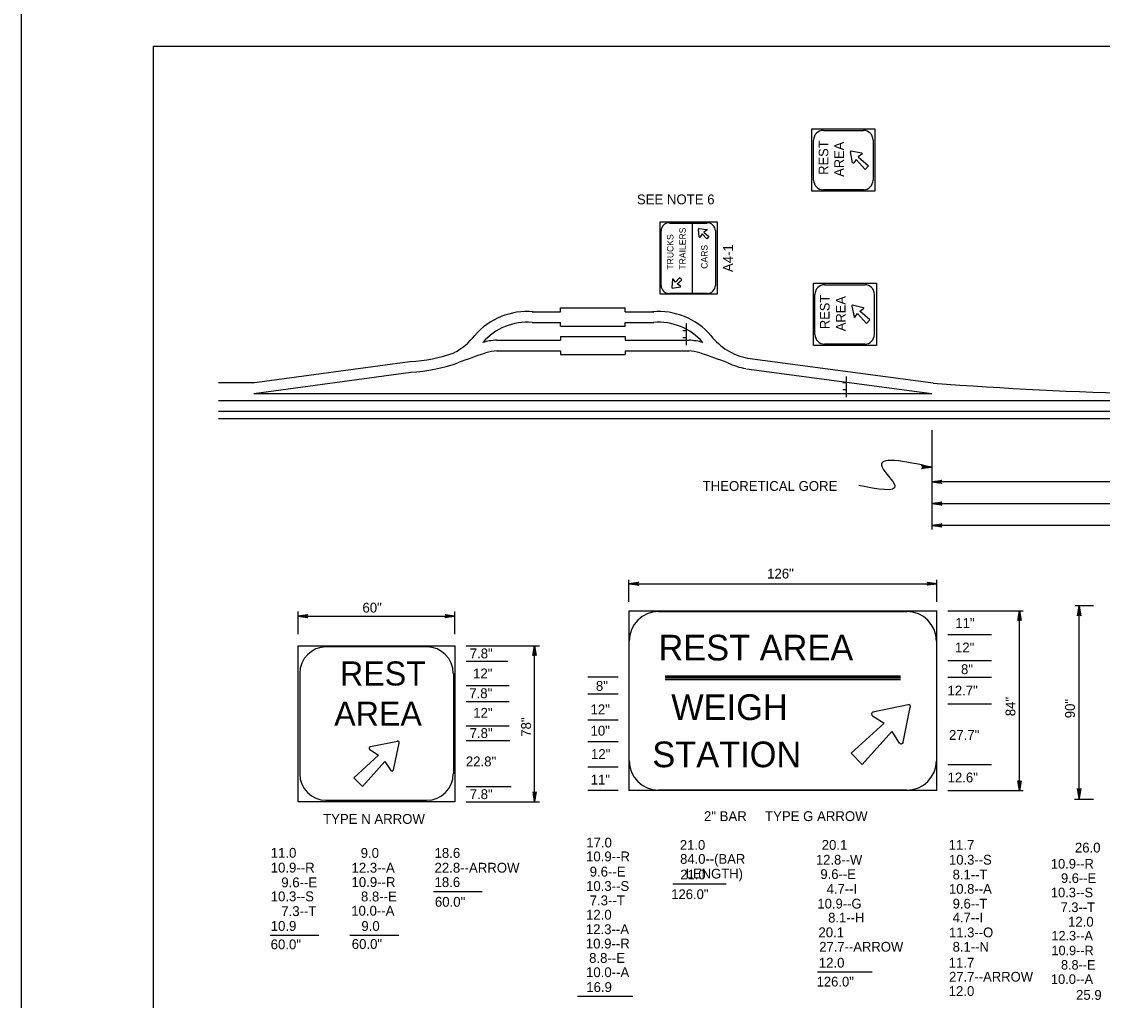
# Model space of a CAD drawing. Extents: x 649604 to 650509, y 298458 to 299646.
# Drawn here: x 649604.3 to 649933.2, y 298746.1 to 299044.1 of the extents above; entities that cross this region are included whole.
import ezdxf

# ---------------------------------------------------------------- set-up
doc = ezdxf.new("R2010")
doc.units = 0
for name, color, linetype in [('1', 7, 'Continuous'), ('2', 7, 'Continuous'), ('3', 7, 'Continuous'), ('PLT-BNDY', 7, 'Continuous')]:
    doc.layers.add(name, color=color, linetype=linetype)

# ---------------------------------------------------------------- blocks, each defined once
blk = doc.blocks.new('RARROW')
at = {"layer": '3'}
blk.add_lwpolyline([(-2.2695, 0.285), (-2.184875, 0.12075), (0, 0), (-2.2695, 0.285), (-2.38575, 0.384625), (0, 0), (-2.183125, -0.108), (-2.262875, -0.2705), (0, 0), (-2.38575, -0.379125), (-2.262875, -0.2705)], dxfattribs=at)

msp = doc.modelspace()

# ---------------------------------------------------------------- linework, layer by layer
at = {"layer": '1'}
for q in [(650430.31, 299036.63), (649644.31, 298472.63)]:
    msp.add_line((649644.31, 299036.63), q, dxfattribs=at)
at = {"layer": '2'}
for p, q in [((649848.31, 299011), (649860.56, 299011)), ((649856.56, 299004.75), (649856.56, 299004.75)), ((649857.19, 299001.13), (649856.56, 299004.5)), ((649856.69, 299004.75), (649860.06, 299004.13)), ((649860.06, 299003.75), (649858.94, 299003)), ((649858.31, 299002.13), (649857.56, 299001.13)), ((649861.06, 298999.13), (649858.31, 299002.13)), ((649858.31, 299002.13), (649858.31, 299002.13)), ((649858.94, 299003), (649858.94, 299003)), ((649858.94, 299003), (649862.06, 299000.25)), ((649862.06, 299000.25), (649861.06, 298999.13)), ((649863.94, 298992.5), (649844.81, 298992.5)), ((649860.56, 298992.88), (649848.31, 298992.88)), ((649801.44, 298982.75), (649812.94, 298982.75)), ((649808.44, 298961.5), (649808.44, 298982.75)), ((649810.56, 298978.63), (649810.31, 298980.88)), ((649810.56, 298981.13), (649812.81, 298980.88)), ((649810.56, 298981), (649810.56, 298981)), ((649812.81, 298980.63), (649811.94, 298980)), ((649812.81, 298980.63), (649812.81, 298980.63)), ((649812.94, 298980.63), (649812.94, 298980.63)), ((649812.94, 298980.63), (649812.94, 298980.63)), ((649810.69, 298978.63), (649810.69, 298978.63)), ((649810.69, 298978.38), (649810.69, 298978.38)), ((649810.69, 298978.38), (649810.69, 298978.38)), ((649811.44, 298979.5), (649810.81, 298978.5)), ((649812.81, 298978), (649811.44, 298979.5)), ((649811.44, 298979.5), (649811.44, 298979.5)), ((649811.69, 298979.75), (649811.69, 298979.75)), ((649811.94, 298980), (649811.94, 298980)), ((649811.94, 298980), (649813.44, 298978.75)), ((649813.44, 298978.75), (649812.81, 298978)), ((649812.81, 298978), (649812.81, 298978)), ((649813.44, 298978.75), (649813.44, 298978.75)), ((649802.44, 298965.63), (649802.19, 298963.25)), ((649802.56, 298965.88), (649802.56, 298965.88)), ((649803.31, 298964.75), (649802.69, 298965.63)), ((649804.56, 298966.13), (649803.31, 298964.75)), ((649803.81, 298964.25), (649805.19, 298965.5)), ((649803.81, 298964.25), (649803.81, 298964.25)), ((649804.81, 298963.63), (649803.81, 298964.25)), ((649805.19, 298965.5), (649804.56, 298966.13)), ((649800.94, 298961.13), (649799.31, 298961.13)), ((649801.44, 298961.5), (649812.94, 298961.5)), ((649802.19, 298963.13), (649802.19, 298963.13)), ((649802.31, 298963), (649804.81, 298963.38)), ((649804.81, 298963.5), (649804.81, 298963.5)), ((649804.81, 298963.5), (649804.81, 298963.5)), ((649808.81, 298961.13), (649807.81, 298961.13)), ((649848.69, 298964), (649860.94, 298964)), ((649856.81, 298957.75), (649856.81, 298957.75)), ((649860.44, 298957), (649857.19, 298957.75)), ((649759.69, 298955.75), (649768.31, 298955.75)), ((649768.31, 298957), (649787.94, 298957)), ((649768.31, 298955.75), (649768.31, 298957)), ((649787.94, 298955.75), (649787.94, 298957)), ((649787.94, 298955.75), (649796.69, 298955.75)), ((649856.94, 298957.5), (649857.69, 298954.25)), ((649857.94, 298954.25), (649858.69, 298955.25)), ((649858.69, 298955.25), (649858.69, 298955.25)), ((649858.69, 298955.25), (649861.44, 298952.25)), ((649859.44, 298956), (649860.56, 298956.75)), ((649862.44, 298953.38), (649859.44, 298956)), ((649859.44, 298956), (649859.44, 298956)), ((649860.94, 298957), (649860.94, 298957)), ((649759.69, 298952.5), (649768.31, 298952.5)), ((649768.31, 298951.38), (649768.31, 298952.5)), ((649768.31, 298951.38), (649787.94, 298951.38)), ((649787.94, 298951.38), (649787.94, 298952.5)), ((649787.94, 298952.5), (649796.69, 298952.5)), ((649806.69, 298945.63), (649806.69, 298952.25)), ((649857.81, 298953.75), (649857.81, 298953.75)), ((649861.44, 298952.25), (649862.44, 298953.38)), ((649768.31, 298948.25), (649787.94, 298948.25)), ((649768.31, 298948.25), (649768.31, 298947.13)), ((649787.94, 298948.25), (649787.94, 298947.13)), ((649806.69, 298950), (649805.56, 298950)), ((649806.69, 298947.88), (649805.56, 298947.88)), ((649748.81, 298947.13), (649768.31, 298947.13)), ((649787.94, 298947.13), (649807.44, 298947.13)), ((649864.44, 298945.5), (649845.31, 298945.5)), ((649860.94, 298945.88), (649848.69, 298945.88)), ((649748.81, 298943.88), (649768.31, 298943.88)), ((649768.31, 298943.88), (649768.31, 298942.75)), ((649768.31, 298942.75), (649787.94, 298942.75)), ((649787.94, 298943.88), (649787.94, 298942.75)), ((649787.94, 298943.88), (649807.44, 298943.88)), ((649825.19, 298941.63), (649881.69, 298934.13)), ((649674.44, 298934.13), (649722.44, 298940.63)), ((649824.94, 298938.38), (649824.94, 298938.38)), ((649824.94, 298938.38), (649881.31, 298930.88)), ((649674.94, 298930.88), (649722.81, 298937.38)), ((649722.81, 298937.38), (649722.81, 298937.38)), ((649722.81, 298937.38), (649722.81, 298937.38)), ((649855.31, 298929.75), (649855.31, 298936.13)), ((649674.94, 298934.13), (649664.19, 298934.13)), ((649855.31, 298934.13), (649854.19, 298934.13)), ((649855.31, 298932), (649854.19, 298932)), ((649664.19, 298928.75), (650390.69, 298928.75)), ((649674.94, 298930.88), (649881.31, 298930.88)), ((649674.94, 298930.88), (649674.94, 298930.88)), ((649674.94, 298930.88), (649674.94, 298930.88)), ((649664.19, 298925.5), (650390.69, 298925.5)), ((649664.19, 298923.25), (650390.69, 298923.25)), ((649881.31, 298919.75), (649881.31, 298889.5)), ((650085.69, 298904), (649881.31, 298904)), ((649881.31, 298897.38), (650176.94, 298897.38)), ((650311.69, 298890.75), (649881.31, 298890.75)), ((649789.13, 298867.47), (649789.13, 298874.13)), ((649789.13, 298873), (649882.88, 298873)), ((649882.88, 298867.47), (649882.88, 298874.13)), ((649930.47, 298866.25), (649924.9, 298866.25)), ((649926.15, 298807.63), (649926.15, 298866.25)), ((649688.44, 298857.65), (649688.44, 298864.5)), ((649688.44, 298863.13), (649736.19, 298863.13)), ((649736.19, 298857.65), (649736.19, 298864.5)), ((649789.13, 298864.75), (649882.88, 298864.75)), ((649789.13, 298864.75), (649789.13, 298810)), ((649798.15, 298864.49), (649873.75, 298864.49)), ((649882.88, 298810), (649882.88, 298864.75)), ((649886.17, 298864.75), (649909.12, 298864.75)), ((649908, 298810), (649908, 298864.75)), ((649886.17, 298857.5), (649899.45, 298857.5)), ((649688.44, 298806.63), (649688.44, 298854.13)), ((649739.56, 298854.13), (649761.94, 298854.13)), ((649760.44, 298806.63), (649760.44, 298854.13)), ((649789.21, 298819.06), (649789.21, 298855.55)), ((649882.7, 298855.55), (649882.7, 298819.06)), ((649739.56, 298849.38), (649752.33, 298849.38)), ((649886.17, 298849.63), (649899.45, 298849.63)), ((649688.94, 298845.63), (649688.94, 298815.13)), ((649735.81, 298815.13), (649735.81, 298845.63)), ((649785.9, 298844.5), (649776.63, 298844.5)), ((649800.13, 298845), (649871.76, 298845)), ((649800.13, 298844.88), (649871.76, 298844.88)), ((649800.13, 298844.5), (649871.76, 298844.5)), ((649800.13, 298844), (649871.76, 298844)), ((649800.13, 298843.88), (649871.76, 298843.88)), ((649886.17, 298844.5), (649899.45, 298844.5)), ((649739.56, 298842), (649752.68, 298842)), ((649785.9, 298839.38), (649776.63, 298839.38)), ((649739.56, 298837.13), (649752.68, 298837.13)), ((649874.13, 298836.13), (649863.38, 298833.88)), ((649874.13, 298836.13), (649863.38, 298833.88)), ((649875.01, 298836.38), (649875.01, 298836.38)), ((649886.17, 298836.38), (649899.45, 298836.38)), ((649862.01, 298833.63), (649862.01, 298833.63)), ((649863.26, 298832.75), (649866.76, 298830.5)), ((649863.26, 298832.75), (649866.76, 298830.5)), ((649872.63, 298824.75), (649874.76, 298835.38)), ((649872.63, 298824.75), (649874.76, 298835.38)), ((649739.56, 298829.75), (649752.68, 298829.75)), ((649785.9, 298831.5), (649776.63, 298831.5)), ((649866.76, 298830.5), (649856.76, 298821.38)), ((649866.76, 298830.5), (649856.76, 298821.38)), ((649866.76, 298830.5), (649866.76, 298830.5)), ((649867.88, 298829.25), (649867.88, 298829.25)), ((649860.13, 298818), (649869.13, 298828)), ((649860.13, 298818), (649869.13, 298828)), ((649869.13, 298828), (649871.38, 298824.5)), ((649869.13, 298828), (649869.13, 298828)), ((649869.13, 298828), (649871.38, 298824.5)), ((649709.31, 298823.13), (649709.31, 298823.13)), ((649718.69, 298825), (649710.44, 298823.38)), ((649717.44, 298816.38), (649719.19, 298824.5)), ((649719.31, 298825.25), (649719.31, 298825.25)), ((649739.56, 298825.25), (649752.91, 298825.25)), ((649785.9, 298824.88), (649776.63, 298824.88)), ((649872.38, 298823.25), (649872.38, 298823.25)), ((649712.94, 298820.75), (649705.44, 298813.88)), ((649710.31, 298822.5), (649712.94, 298820.75)), ((649712.94, 298820.75), (649712.94, 298820.75)), ((649856.76, 298821.38), (649860.13, 298818)), ((649856.76, 298821.38), (649856.76, 298821.38)), ((649856.76, 298821.38), (649860.13, 298818)), ((649708.06, 298811.25), (649714.81, 298818.88)), ((649714.81, 298818.88), (649714.81, 298818.88)), ((649714.81, 298818.88), (649716.69, 298816.13)), ((649785.9, 298817.13), (649776.63, 298817.13)), ((649860.13, 298818), (649860.13, 298818)), ((649886.17, 298818), (649899.45, 298818)), ((649705.44, 298813.88), (649708.06, 298811.25)), ((649717.19, 298815.25), (649717.19, 298815.25)), ((649739.56, 298811.25), (649753.26, 298811.25)), ((649785.9, 298810), (649776.63, 298810)), ((649882.88, 298810), (649789.13, 298810)), ((649873.75, 298810.12), (649798.15, 298810.12)), ((649886.17, 298810), (649909.12, 298810)), ((649739.56, 298806.63), (649761.94, 298806.63)), ((649930.47, 298807.27), (649924.77, 298807.27)), ((649802.47, 298781.61), (649818.72, 298781.61)), ((649729.65, 298779.34), (649744.51, 298779.34)), ((649679.92, 298765.97), (649694.77, 298765.97)), ((649704.19, 298765.97), (649719.1, 298765.97)), ((649846.53, 298754.86), (649863.15, 298754.86)), ((649773.49, 298747.38), (649790.28, 298747.38))]:
    msp.add_line(p, q, dxfattribs=at)
for points in [[(649844.81, 298992.5), (649844.81, 299011.5), (649846.81, 299011.5), (649849.81, 299011.5), (649851.69, 299011.5), (649854.56, 299011.5), (649856.56, 299011.5), (649862.19, 299011.5), (649863.94, 299011.5), (649863.94, 299011.5), (649863.94, 298992.5), (649863.94, 298992.5)], [(649845.31, 298995.88), (649845.31, 299008.13)], [(649863.44, 299008.13), (649863.44, 298995.88)], [(649798.69, 298961.13), (649798.69, 298983.13), (649800.31, 298983.13), (649802.19, 298983.13), (649803.69, 298983.13), (649805.69, 298983.13), (649807.06, 298983.13), (649808.56, 298983.13), (649811.81, 298983.13), (649815.94, 298983.13), (649815.94, 298961.13), (649811.19, 298961.13), (649809.31, 298961.13), (649807.06, 298961.13), (649804.69, 298961.13), (649801.44, 298961.13), (649798.69, 298961.13)], [(649798.94, 298963.75), (649798.94, 298980.5)], [(649815.44, 298980.5), (649815.44, 298963.75)], [(649845.31, 298945.5), (649845.31, 298964.5), (649847.31, 298964.5), (649850.19, 298964.5), (649852.06, 298964.5), (649855.06, 298964.5), (649856.81, 298964.5), (649862.56, 298964.5), (649864.44, 298964.5), (649864.44, 298964.5), (649864.44, 298945.5), (649864.44, 298945.5)], [(649845.69, 298948.88), (649845.69, 298961.13)], [(649863.81, 298961.13), (649863.81, 298948.88)], [(649688.44, 298854.13), (649736.19, 298854.13), (649736.19, 298849.38), (649736.19, 298842), (649736.19, 298837.13), (649736.19, 298829.75), (649736.19, 298825.25), (649736.19, 298811.25), (649736.19, 298806.63), (649736.19, 298806.63), (649688.44, 298806.63), (649688.44, 298806.63)], [(649727.56, 298853.75), (649696.94, 298853.75)], [(649696.94, 298807.13), (649727.56, 298807.13)]]:
    msp.add_lwpolyline(points, dxfattribs=at)
for centre, radius, start, end in [((649848.27, 299008.08), 2.93, 90, 180), ((649860.49, 299008.08), 2.93, 0, 90), ((649856.7, 299004.54), 0.183, 78.0958, 191.9043), ((649856.7, 299004.54), 0.183, 78.0958, 191.9043), ((649859.98, 299003.85), 0.183, 302.692, 78.0958), ((649859.98, 299003.85), 0.183, 302.692, 78.0958), ((649857.39, 299001.26), 0.183, 191.9043, 327.308), ((649857.39, 299001.26), 0.183, 191.9042, 327.308), ((649848.27, 298995.86), 2.93, 180, 270), ((649860.49, 298995.86), 2.93, 270, 0), ((649801.36, 298980.44), 2.44, 90, 180), ((649810.44, 298981), 0.153, 84.0498, 185.9502), ((649812.84, 298980.75), 0.153, 301.5539, 84.0498), ((649812.99, 298980.44), 2.44, 0, 90), ((649810.69, 298978.6), 0.153, 185.9502, 328.4461), ((649802.55, 298965.61), 0.153, 31.5539, 174.0498), ((649801.36, 298963.82), 2.44, 180, 270), ((649802.3, 298963.22), 0.153, 174.0498, 275.9502), ((649804.69, 298963.47), 0.153, 275.9502, 58.4461), ((649812.99, 298963.82), 2.44, 270, 0), ((649848.69, 298961.09), 2.93, 90, 180), ((649860.91, 298961.09), 2.93, 0, 90), ((649857.12, 298957.56), 0.183, 78.0958, 191.9043), ((649857.12, 298957.56), 0.183, 78.0958, 191.9043), ((649758.25, 298934.67), 21.21, 85.4134, 139.1043), ((649798.05, 298934.67), 21.21, 40.8957, 94.5866), ((649857.81, 298954.27), 0.183, 191.9043, 327.308), ((649857.81, 298954.27), 0.183, 191.9043, 327.308), ((649860.4, 298956.87), 0.183, 302.692, 78.0958), ((649860.4, 298956.87), 0.183, 302.692, 78.0958), ((649758.25, 298934.67), 17.95, 85.4134, 139.1043), ((649798.05, 298934.67), 17.95, 40.8957, 94.5866), ((649727.53, 298959.9), 18.56, 296.8793, 322.3109), ((649828.77, 298959.9), 18.56, 217.6891, 259.2048), ((649848.69, 298948.87), 2.93, 180, 270), ((649860.91, 298948.87), 2.93, 270, 0), ((649749.74, 298929.33), 17.82, 92.9526, 106.4866), ((649806.56, 298929.33), 17.82, 73.5134, 87.0474), ((649719.77, 298988.56), 48.03, 273.3346, 289.6636), ((651988.02, 292598.03), 6729.85, 109.463364, 109.540836), ((649749.74, 298929.33), 14.56, 92.9526, 106.4866), ((649806.56, 298929.33), 14.56, 73.5134, 87.0474), ((647568.28, 292598.03), 6729.85, 70.459164, 70.536636), ((649719.77, 298988.56), 51.29, 273.3346, 289.6636), ((649828.77, 298959.9), 21.82, 244.1957, 259.2048), ((649975.83, 300169.06), 1238.57, 265.6447, 268.64351), ((649798.15, 298855.55), 8.94, 90, 180), ((649873.75, 298855.55), 8.94, 0, 90), ((649697.03, 298845.68), 8.08, 90, 180), ((649727.58, 298845.68), 8.08, 0, 90), ((649874.21, 298835.48), 0.659, 348.2602, 101.7398), ((649874.21, 298835.48), 0.659, 348.2602, 101.7398), ((649863.63, 298833.28), 0.659, 101.7398, 236.6838), ((649863.63, 298833.28), 0.659, 101.7398, 236.6838), ((649710.53, 298822.89), 0.458, 101.9043, 237.308), ((649710.53, 298822.89), 0.458, 101.9043, 237.308), ((649718.74, 298824.62), 0.458, 348.0958, 101.9043), ((649718.74, 298824.62), 0.458, 348.0958, 101.9043), ((649872.01, 298824.9), 0.659, 213.3162, 348.2602), ((649872.01, 298824.9), 0.659, 213.3162, 348.2602), ((649717.01, 298816.41), 0.458, 212.692, 348.0958), ((649717.01, 298816.41), 0.458, 212.692, 348.0957), ((649798.15, 298819.06), 8.94, 180, 270), ((649873.75, 298819.06), 8.94, 270, 0), ((649697.03, 298815.13), 8.08, 180, 270), ((649727.58, 298815.13), 8.08, 270, 0)]:
    msp.add_arc(centre, radius, start, end, dxfattribs=at)
msp.add_spline([(649881.31, 298908.5), (649866.19, 298908.5), (649870.06, 298902.88), (649859.06, 298902.88)], degree=3, dxfattribs=at)
at = {"layer": 'PLT-BNDY'}
msp.add_lwpolyline([(649604.31, 299051.63), (650445.31, 299051.63), (650445.31, 298457.63), (649604.31, 298457.63)], close=True, dxfattribs=at)

# ---------------------------------------------------------------- block references
at = {"layer": '2', "xscale": 1.2574347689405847, "yscale": 1.3092961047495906}
for p in [(649881.17, 298908.48), (649882.88, 298873), (649736.19, 298863.13)]:
    msp.add_blockref('RARROW', p, dxfattribs=at)
for p, rotation in [((649881.31, 298904), 180), ((649881.31, 298897.38), 180), ((649881.31, 298890.75), 180), ((649789.13, 298873), 180), ((649926.15, 298866.25), 89.99999999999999), ((649688.44, 298863.13), 180), ((649908, 298864.75), 89.99999999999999), ((649760.44, 298854.13), 89.99999999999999), ((649908, 298810), -90.00000000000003), ((649760.44, 298806.63), -90.00000000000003), ((649926.15, 298807.63), -90.00000000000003)]:
    msp.add_blockref('RARROW', p, dxfattribs=dict(at, rotation=rotation))

# ---------------------------------------------------------------- texts
at = {"layer": '2'}
for s, height, p in [('REST', 2.932, (649849.81, 298997.5)), ('AREA', 2.932, (649854.56, 298996.88)), ('TRAILERS', 1.955, (649806.44, 298968.63)), ('TRUCKS', 1.955, (649802.69, 298968.63)), ('CARS', 1.955, (649813.06, 298968.88)), ('A4-1', 3, (649820.81, 298967.88)), ('REST', 2.932, (649850.19, 298950.5)), ('AREA', 2.932, (649855.06, 298949.88)), ('84"', 3, (649906.74, 298832.66)), ('90"', 3, (649924.86, 298832.03)), ('78"', 3, (649759.35, 298826.39))]:
    msp.add_text(s, height=height, rotation=90, dxfattribs=at).set_placement(p)
for s, height, p in [('SEE NOTE 6', 3, (649791.56, 298988.5)), ('THEORETICAL GORE', 3, (649811.56, 298901.25)), ('126"', 3, (649831.2, 298874.58)), ('60"', 3, (649708.04, 298864.21)), ('11"', 3, (649888.44, 298859.52)), ('REST AREA', 7.82, (649798.13, 298849.63)), ('7.8"', 3, (649740.68, 298850.28)), ('12"', 3, (649888.35, 298852.07)), ('REST', 7.33, (649701.19, 298842)), ('12"', 3, (649741.71, 298844.17)), ('8"', 3, (649890.19, 298845.47)), ('8"', 3, (649779.08, 298840.38)), ('7.8"', 3, (649740.54, 298838.15)), ('WEIGH', 7.82, (649802.01, 298831.5)), ('12.7"', 3, (649886.08, 298838.97)), ('AREA', 7.33, (649699.44, 298829.75)), ('12"', 3, (649777.45, 298833.25)), ('12"', 3, (649741.75, 298832.18)), ('10"', 3, (649777.45, 298826.75)), ('7.8"', 3, (649740.65, 298826.02)), ('27.7"', 3, (649886.54, 298825.46)), ('12"', 3, (649777.59, 298819.63)), ('STATION', 7.82, (649796.26, 298817.13)), ('22.8"', 3, (649739.51, 298817.39)), ('11"', 3, (649777.5, 298811.86)), ('12.6"', 3, (649886.1, 298812.5)), ('7.8"', 3, (649740.68, 298807.42)), ('2" BAR     TYPE G ARROW', 3, (649811.97, 298800.73)), ('TYPE N ARROW', 3, (649696.06, 298799.88)), ('17.0   ', 3, (649776.14, 298792.69)), ('21.0             ', 2.9663, (649804.64, 298791.98)), ('20.1      ', 3, (649847.8, 298791.98)), ('11.7       ', 3, (649886.43, 298791.98)), ('26.0', 3, (649924.85, 298791.15)), ('11.0   ', 3, (649680.12, 298789.56)), ('9.0   ', 3, (649707.5, 298789.53)), ('18.6       ', 3, (649729.98, 298789.53)), ('10.9--R', 3, (649776.08, 298788.47)), ('84.0--(BAR', 2.966, (649804.71, 298787.72)), (' 12.8--W    ', 2.9663, (649844.94, 298787.48)), ('10.3--S    ', 2.9663, (649886.55, 298787.48)), ('10.9--R', 3, (649680.12, 298785.06)), ('12.3--A', 3, (649704.71, 298785.03)), ('22.8--ARROW', 3, (649729.98, 298785.03)), (' 9.6--E', 3, (649776.08, 298783.84)), ('    10.9--R', 2.931, (649913.19, 298786.27)), ('9.6--E', 3, (649683.34, 298780.56)), ('10.9--R', 3, (649704.71, 298780.66)), ('18.6       ', 3, (649729.98, 298780.65)), ('21.0', 2.966, (649804.76, 298782.98)), ('         LENGTH)', 2.9663, (649796.5, 298783.25)), ('  9.6--E     ', 2.9663, (649845.2, 298783.1)), (' 8.1--T    ', 2.9663, (649886.55, 298782.98)), ('    9.6--E', 2.931, (649916.27, 298781.9)), ('10.3--S', 3, (649776.08, 298779.47)), ('126.0"             ', 2.9663, (649802.01, 298776.98)), (' 4.7--I    ', 2.9663, (649848.21, 298778.61)), ('10.8--A    ', 2.9663, (649886.55, 298778.61)), ('    10.3--S', 2.931, (649913.19, 298777.52)), ('10.3--S', 3, (649680.12, 298776.31)), ('8.8--E', 3, (649707.59, 298776.28)), ('60.0"        ', 3, (649730.09, 298774.65)), (' 7.3--T', 3, (649776.08, 298775.09)), (' 10.9--G    ', 2.9663, (649845.39, 298774.11)), (' 9.6--T    ', 2.9663, (649886.55, 298774.11)), ('7.3--T', 3, (649683.34, 298771.81)), ('10.0--A', 3, (649704.62, 298771.94)), ('12.0   ', 3, (649776.08, 298770.72)), ('    7.3--T', 2.931, (649916.15, 298773.03)), ('10.9   ', 3, (649680.12, 298767.31)), ('9.0   ', 3, (649707.71, 298767.28)), (' 8.1--H    ', 2.9663, (649848.66, 298769.86)), (' 4.7--I    ', 2.9663, (649886.55, 298769.86)), (' 12.0', 3, (649921.65, 298768.58)), ('12.3--A', 3, (649776.02, 298766.31)), (' 20.1       ', 3, (649845.69, 298765.36)), ('11.3--O    ', 2.9663, (649886.55, 298765.36)), ('    12.3--A', 2.8748, (649913.47, 298764.4)), ('60.0"    ', 3, (649680.1, 298761.69)), ('60.0"    ', 3, (649704.78, 298761.81)), ('10.9--R', 3, (649776.02, 298761.94)), (' 27.7--ARROW', 2.9663, (649845.95, 298760.98)), (' 8.1--N    ', 2.9663, (649886.55, 298760.98)), (' 8.8--E', 3, (649775.9, 298757.56)), ('    10.9--R', 2.8748, (649913.47, 298759.9)), (' 12.0       ', 3, (649845.81, 298756.11)), ('11.7       ', 3, (649886.43, 298756.11)), ('    8.8--E', 2.875, (649916.36, 298755.52)), ('10.0--A', 3, (649776.08, 298753.22)), ('27.7--ARROW', 2.9663, (649886.55, 298751.86)), ('    10.0--A', 2.931, (649913.19, 298751.15)), ('16.9   ', 3, (649776.14, 298748.69)), ('126.0"       ', 2.9663, (649846.25, 298750.36)), ('12.0', 3, (649886.44, 298747.48)), ('25.9', 3, (649925.2, 298746.31))]:
    msp.add_text(s, height=height, dxfattribs=at).set_placement(p)

doc.saveas('drawing.dxf')
